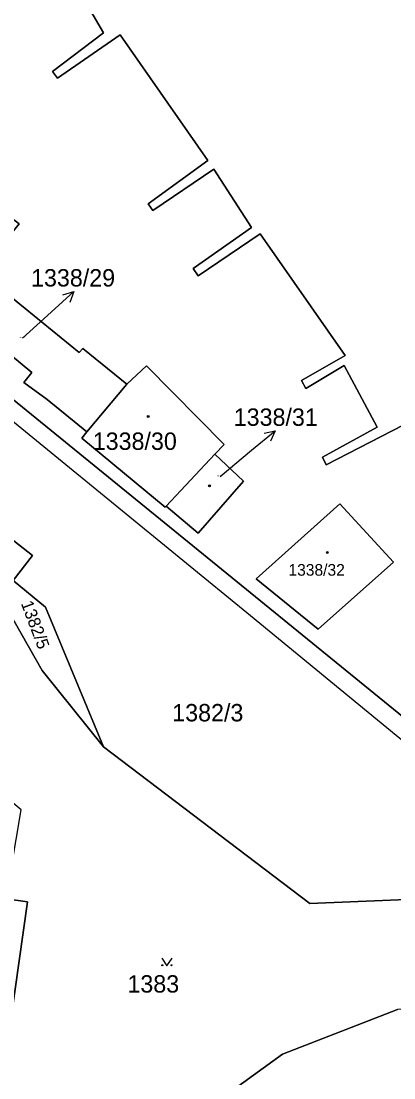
# Model space of a CAD drawing. Extents: x -598934 to -598196, y -1162208 to -1161502.
# Drawn here: x -598418.7 to -598382.2, y -1161993.6 to -1161890.3 of the extents above; entities that cross this region are included whole.
import ezdxf

# ---------------------------------------------------------------- set-up
doc = ezdxf.new("R2010")
doc.units = 0
for name, color, linetype in [('KN_CAR_KR', 7, 'Continuous'), ('KN_KULTURY', 7, 'Continuous'), ('KN_PARC_CIS_POM', 7, 'Continuous'), ('KN_PARC_CIS_POZ', 7, 'Continuous'), ('KN_PARC_CIS_STAV', 7, 'Continuous'), ('KN_PARC_PLOCHA', 7, 'Continuous'), ('PARC_C_SIPKA', 7, 'Continuous'), ('parcely_l', 7, 'Continuous')]:
    doc.layers.add(name, color=color, linetype=linetype)

msp = doc.modelspace()

# ---------------------------------------------------------------- linework, layer by layer
at = {"layer": 'KN_CAR_KR'}
for points in [[(-598449.09, -1161905.21), (-598416.08, -1161932.19)], [(-598416.08, -1161932.19), (-598396.26, -1161948.42)], [(-598396.26, -1161948.42), (-598368.68, -1161971.07)]]:
    msp.add_lwpolyline(points, dxfattribs=at)
at = {"layer": 'KN_KULTURY'}
msp.add_lwpolyline([(-598404.92, -1161981.92), (-598404.42, -1161982.67), (-598403.92, -1161981.92)], dxfattribs=at)
for centre, radius in [((-598406.24, -1161928.98), 0.09), ((-598406.24, -1161928.98), 0.0398), ((-598400.25, -1161935.76), 0.09), ((-598400.25, -1161935.76), 0.0398), ((-598388.74, -1161942.27), 0.09), ((-598388.74, -1161942.27), 0.0398), ((-598404.87, -1161982.62), 0.05), ((-598403.97, -1161982.62), 0.05)]:
    msp.add_circle(centre, radius, dxfattribs=at)
at = {"layer": 'KN_PARC_PLOCHA'}
for points in [[(-598366.78, -1161975.62), (-598390.45, -1161976.59), (-598410.61, -1161961.27), (-598416.3, -1161947.61), (-598419.46, -1161945.01), (-598417.56, -1161942.55), (-598544.13, -1161843.14), (-598559.82, -1161830.33)], [(-598418.63, -1161877.72), (-598410.62, -1161891.48), (-598415.61, -1161895.25), (-598415.12, -1161895.92), (-598408.98, -1161891.67), (-598400.43, -1161903.94), (-598406.24, -1161908.18), (-598405.79, -1161908.83), (-598399.82, -1161904.79), (-598396.14, -1161910.5), (-598401.85, -1161914.5), (-598401.36, -1161915.22), (-598395.32, -1161911.12), (-598387, -1161923.02), (-598391.25, -1161925.46), (-598390.83, -1161926.24), (-598387.08, -1161923.98), (-598383.86, -1161930.02), (-598389.21, -1161932.96), (-598388.87, -1161933.7), (-598380.24, -1161929.28)], [(-598380.24, -1161929.28), (-598388.87, -1161933.7), (-598389.21, -1161932.96), (-598383.86, -1161930.02), (-598387.08, -1161923.98), (-598390.83, -1161926.24), (-598391.25, -1161925.46), (-598387, -1161923.02), (-598395.32, -1161911.12), (-598401.36, -1161915.22), (-598401.85, -1161914.5), (-598396.14, -1161910.5), (-598399.82, -1161904.79), (-598405.79, -1161908.83), (-598406.24, -1161908.18), (-598400.43, -1161903.94), (-598408.98, -1161891.67), (-598415.12, -1161895.92), (-598415.61, -1161895.25), (-598410.62, -1161891.48), (-598418.63, -1161877.72)], [(-598460.63, -1161890.21), (-598461.81, -1161892.42), (-598459.01, -1161894.6), (-598450.04, -1161902.22), (-598445.31, -1161906.14), (-598437.34, -1161912.74), (-598432.57, -1161916.66), (-598370.19, -1161967.44)], [(-598426.55, -1161917.32), (-598417.64, -1161924.66), (-598418.42, -1161925.65), (-598416.11, -1161927.31), (-598412.25, -1161930.49), (-598412.73, -1161931.08), (-598404.6, -1161937.84), (-598404.5, -1161937.73), (-598401.36, -1161940.39), (-598396.92, -1161935.29), (-598399.73, -1161932.66), (-598398.84, -1161931.71), (-598406.43, -1161924.03), (-598408.33, -1161925.81), (-598412.65, -1161922.34), (-598412.99, -1161922.72), (-598422.7, -1161914.85)], [(-598370.19, -1161967.44), (-598432.57, -1161916.66)], [(-598381.89, -1161986.93), (-598393.12, -1161991.3), (-598401.64, -1161997.46), (-598416.88, -1162003.6), (-598427.44, -1162004.06), (-598426.91, -1162001.11), (-598433.33, -1162000.37), (-598432.98, -1161997.71), (-598421.33, -1161999.5), (-598418.06, -1161976.42), (-598420.12, -1161976.12), (-598418.67, -1161967.42), (-598426.93, -1161960.53), (-598427.12, -1161961.64), (-598430.57, -1161958.96), (-598425.35, -1161952.41), (-598423.59, -1161950.19), (-598420.71, -1161946.57), (-598416.62, -1161953.81), (-598410.61, -1161961.27), (-598390.45, -1161976.59), (-598366.78, -1161975.62)], [(-598557.04, -1161982.63), (-598544.66, -1161987.36), (-598527.93, -1161992.85), (-598508.13, -1161998.08), (-598492.8, -1162000.75), (-598472.89, -1162003.52), (-598452.19, -1162006.44), (-598434.72, -1162008.36), (-598429.78, -1162008.15), (-598420.93, -1162007.01), (-598412.69, -1162004.16), (-598406.14, -1162000.56), (-598401.64, -1161997.46), (-598393.12, -1161991.3), (-598381.89, -1161986.93)]]:
    msp.add_lwpolyline(points, dxfattribs=at)
for points in [[(-598419.46, -1161945.01), (-598434.23, -1161932.91), (-598456.82, -1161914.47), (-598480.01, -1161895.48), (-598488.77, -1161888.33), (-598509.93, -1161871.06), (-598526.36, -1161857.65), (-598529.72, -1161854.91), (-598540.9, -1161845.79), (-598544.13, -1161843.14), (-598417.56, -1161942.55)], [(-598408.33, -1161925.81), (-598412.25, -1161930.49), (-598416.11, -1161927.31), (-598418.42, -1161925.65), (-598417.64, -1161924.66), (-598426.55, -1161917.32), (-598430.52, -1161914.26), (-598430.12, -1161913.78), (-598429.91, -1161914.03), (-598427.44, -1161910.98), (-598426.01, -1161909.35), (-598426.29, -1161909.1), (-598423.94, -1161906.37), (-598418.86, -1161910.13), (-598422.7, -1161914.85), (-598412.99, -1161922.72), (-598412.65, -1161922.34)], [(-598399.73, -1161932.66), (-598404.5, -1161937.73), (-598404.6, -1161937.84), (-598412.73, -1161931.08), (-598412.25, -1161930.49), (-598408.33, -1161925.81), (-598406.43, -1161924.03), (-598398.84, -1161931.71)], [(-598404.5, -1161937.73), (-598399.73, -1161932.66), (-598396.92, -1161935.29), (-598401.36, -1161940.39)], [(-598382.26, -1161943.22), (-598389.64, -1161949.76), (-598395.69, -1161944.85), (-598387.52, -1161937.53)], [(-598382.26, -1161943.22), (-598387.52, -1161937.53), (-598395.69, -1161944.85), (-598389.64, -1161949.76)], [(-598410.61, -1161961.27), (-598416.62, -1161953.81), (-598420.71, -1161946.57), (-598419.46, -1161945.01), (-598416.3, -1161947.61)], [(-598428.92, -1161974.66), (-598420.12, -1161976.12), (-598418.06, -1161976.42), (-598421.33, -1161999.5), (-598432.98, -1161997.71), (-598429.41, -1161975.88), (-598429.32, -1161975.19), (-598429.27, -1161974.61)]]:
    msp.add_lwpolyline(points, close=True, dxfattribs=at)
at = {"layer": 'PARC_C_SIPKA'}
for points in [[(-598418.53, -1161921.31), (-598415.74, -1161918.79), (-598413.52, -1161916.77)], [(-598414.59, -1161917.08), (-598413.52, -1161916.77), (-598413.92, -1161917.82)], [(-598399.22, -1161934.83), (-598396.14, -1161932.28), (-598393.83, -1161930.37)], [(-598394.92, -1161930.62), (-598393.83, -1161930.37), (-598394.28, -1161931.39)]]:
    msp.add_lwpolyline(points, dxfattribs=at)
at = {"layer": 'parcely_l'}
for points in [[(-598544.13, -1161843.14), (-598417.56, -1161942.55), (-598419.46, -1161945.01)], [(-598380.24, -1161929.28), (-598388.87, -1161933.7), (-598389.21, -1161932.96), (-598383.86, -1161930.02), (-598387.08, -1161923.98), (-598390.83, -1161926.24), (-598391.25, -1161925.46), (-598387, -1161923.02), (-598395.32, -1161911.12), (-598401.36, -1161915.22), (-598401.85, -1161914.5), (-598396.14, -1161910.5), (-598399.82, -1161904.79), (-598405.79, -1161908.83), (-598406.24, -1161908.18), (-598400.43, -1161903.94), (-598408.98, -1161891.67), (-598415.12, -1161895.92), (-598415.61, -1161895.25), (-598410.62, -1161891.48), (-598418.63, -1161877.72)], [(-598408.33, -1161925.81), (-598412.65, -1161922.34), (-598412.99, -1161922.72), (-598422.7, -1161914.85), (-598418.86, -1161910.13), (-598423.94, -1161906.37)], [(-598430.52, -1161914.26), (-598426.55, -1161917.32), (-598417.64, -1161924.66), (-598418.42, -1161925.65), (-598416.11, -1161927.31), (-598412.25, -1161930.49)], [(-598370.19, -1161967.44), (-598432.57, -1161916.66)], [(-598408.33, -1161925.81), (-598406.43, -1161924.03), (-598398.84, -1161931.71), (-598399.73, -1161932.66)], [(-598412.25, -1161930.49), (-598408.33, -1161925.81)], [(-598404.5, -1161937.73), (-598404.6, -1161937.84), (-598412.73, -1161931.08), (-598412.25, -1161930.49)], [(-598399.73, -1161932.66), (-598404.5, -1161937.73)], [(-598399.73, -1161932.66), (-598396.92, -1161935.29), (-598401.36, -1161940.39), (-598404.5, -1161937.73)], [(-598382.26, -1161943.22), (-598387.52, -1161937.53), (-598395.69, -1161944.85), (-598389.64, -1161949.76), (-598382.26, -1161943.22)], [(-598419.46, -1161945.01), (-598416.3, -1161947.61), (-598410.61, -1161961.27)], [(-598410.61, -1161961.27), (-598416.62, -1161953.81), (-598420.71, -1161946.57)], [(-598410.61, -1161961.27), (-598390.45, -1161976.59), (-598366.78, -1161975.62)], [(-598420.12, -1161976.12), (-598418.06, -1161976.42), (-598421.33, -1161999.5), (-598432.98, -1161997.71)], [(-598361.9, -1161985.65), (-598369.78, -1161985.86), (-598381.89, -1161986.93), (-598393.12, -1161991.3), (-598401.64, -1161997.46)]]:
    msp.add_lwpolyline(points, dxfattribs=at)

# ---------------------------------------------------------------- texts
at = {"layer": 'KN_PARC_CIS_POM'}
for s, p in [('1338/29', (-598418.86, -1161921.31)), ('1338/31', (-598399.55, -1161934.83))]:
    msp.add_text(s, height=0.1, dxfattribs=at).set_placement(p)
at = {"layer": 'KN_PARC_CIS_POZ'}
msp.add_text('1382/5', height=1.2, rotation=290.6999, dxfattribs=at).set_placement((-598418.71, -1161947.24))
for s, p in [('1382/3', (-598403.9, -1161958.78)), ('1383', (-598408.28, -1161985.29))]:
    msp.add_text(s, height=1.7, dxfattribs=at).set_placement(p)
at = {"layer": 'KN_PARC_CIS_STAV'}
for s, height, p in [('1338/29', 1.7, (-598417.7, -1161916.27)), ('1338/31', 1.7, (-598397.89, -1161929.89)), ('1338/30', 1.7, (-598411.67, -1161932.24)), ('1338/32', 1.14, (-598392.54, -1161944.54))]:
    msp.add_text(s, height=height, dxfattribs=at).set_placement(p)

doc.saveas('drawing.dxf')
